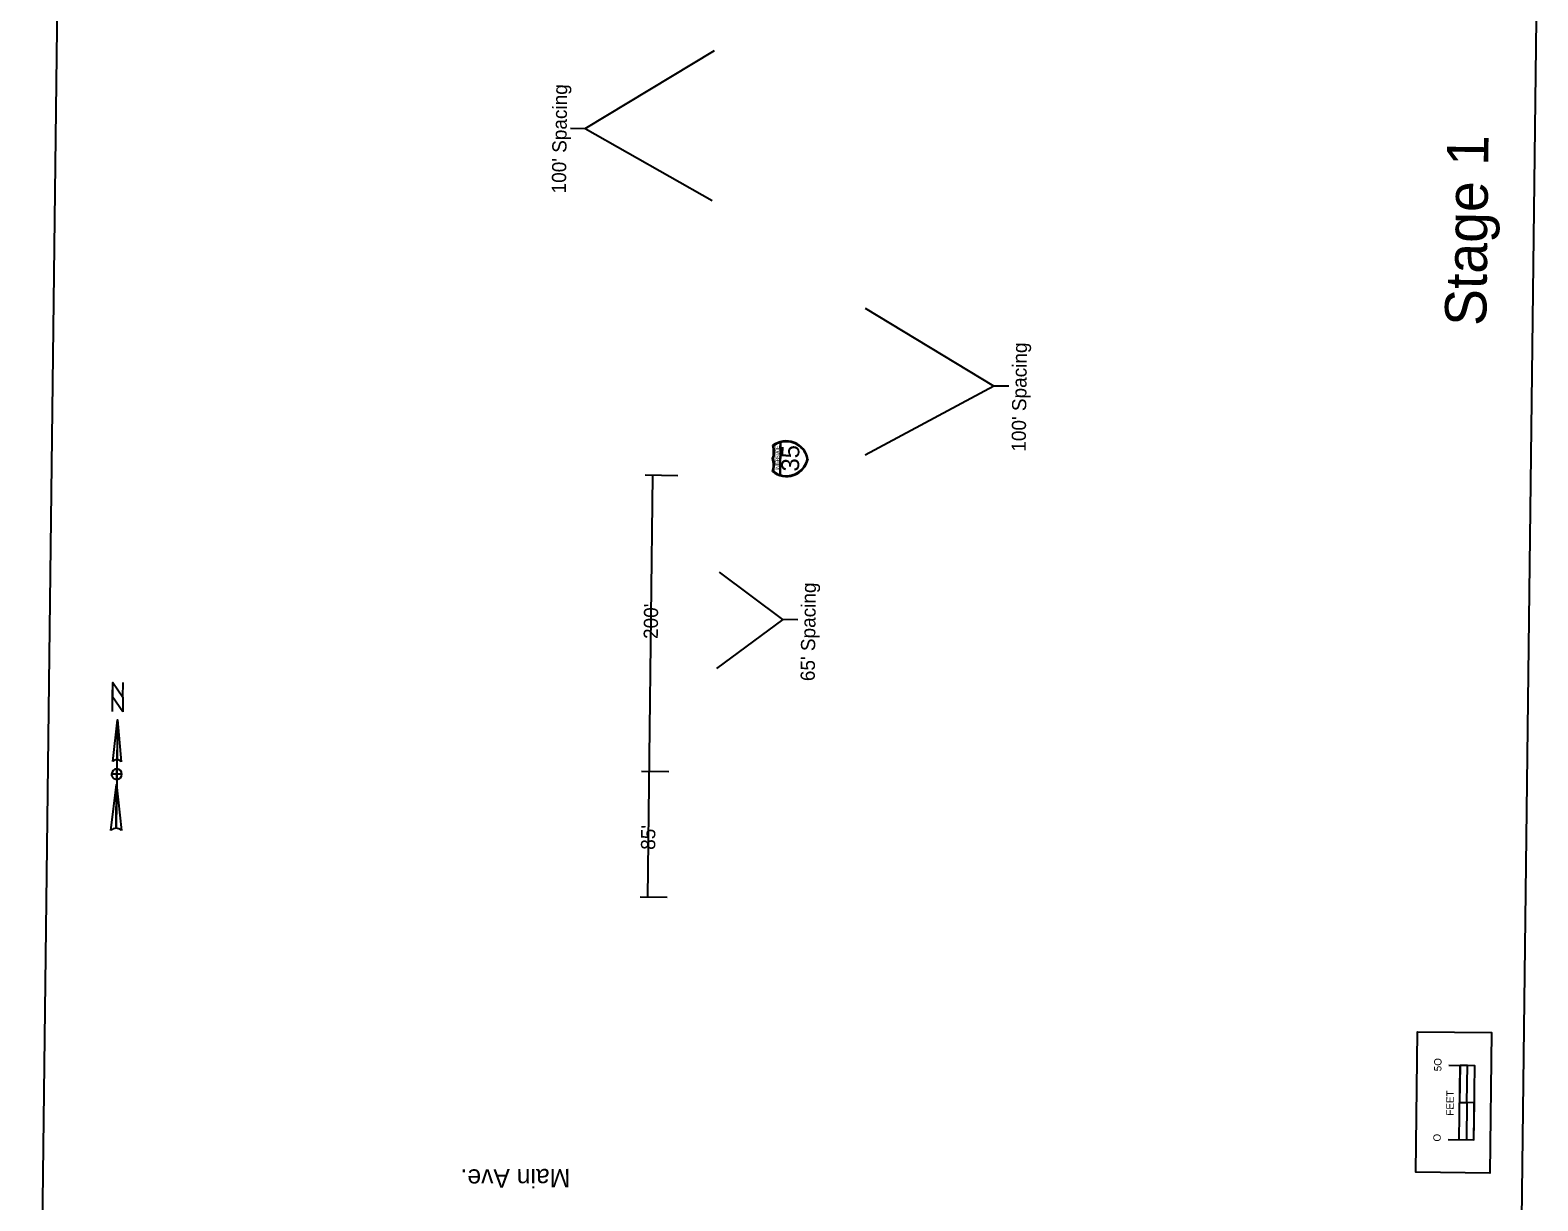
# Model space of a CAD drawing. Extents: x 4959127 to 4960275, y 3872379 to 3884458.
# Drawn here: x 4959182 to 4960201, y 3877574 to 3878365 of the extents above; entities that cross this region are included whole.
import ezdxf

# ---------------------------------------------------------------- set-up
doc = ezdxf.new("R2010")
doc.units = 0
for name, color, linetype in [('Cell', 7, 'Continuous'), ('dsnCellElements', 7, 'Continuous'), ('dsnCellsHighwaySymbols', 7, 'Continuous'), ('dsnCellsScaleBlock', 7, 'Continuous'), ('NamedBoundary', 7, 'Continuous'), ('SheetText', 7, 'Continuous'), ('Text', 7, 'Continuous')]:
    doc.layers.add(name, color=color, linetype=linetype)

msp = doc.modelspace()

# ---------------------------------------------------------------- linework, layer by layer
at = {"layer": 'Cell'}
for p, q in [((4959241.1, 3877898.6), (4959240.2, 3877825.4)), ((4959241.1, 3877898.6), (4959243.5, 3877870.4)), ((4959237.9, 3877870.5), (4959237.9, 3877870.5)), ((4959238, 3877870.7), (4959238.5, 3877871.3)), ((4959240.6, 3877858.5), (4959240.6, 3877858.5)), ((4959236.6, 3877824), (4959240.5, 3877855))]:
    msp.add_line(p, q, dxfattribs=at)
for points in [[(4959237.6, 3877904.3), (4959237.9, 3877924), (4959244.8, 3877914.1), (4959244.9, 3877923.9)], [(4959237.9, 3877870.5), (4959241.1, 3877898.6), (4959240.7, 3877871.9)], [(4959240.6, 3877858.5), (4959240.6, 3877862), (4959237.1, 3877862)], [(4959244.1, 3877862), (4959240.6, 3877862), (4959240.7, 3877865.5)], [(4959240.2, 3877825.4), (4959240.5, 3877855), (4959243.7, 3877823.9)]]:
    msp.add_lwpolyline(points, dxfattribs=at)
msp.add_lwpolyline([(4959244.7, 3877904.2), (4959237.7, 3877914.2), (4959237.9, 3877924), (4959244.8, 3877914.1)], close=True, dxfattribs=at)
for centre, radius, start, end in [((4959240.7, 3877868.3), 3.52, 89.3179, 142.4233), ((4959240.7, 3877868.3), 3.52, 36.1456, 89.3194), ((4959240.6, 3877862), 3.52, 89.2975, 179.2975), ((4959240.6, 3877862), 3.52, 179.2975, 269.2975), ((4959240.6, 3877862), 3.52, 269.2975, 359.2975), ((4959240.6, 3877862), 3.52, 359.2975, 89.2975), ((4959240.1, 3877820.3), 5.1, 89.2869, 132.9165), ((4959240.1, 3877820.3), 5.11, 45.6996, 89.2982)]:
    msp.add_arc(centre, radius, start, end, dxfattribs=at)
at = {"layer": 'dsnCellElements'}
msp.add_lwpolyline([(4960118.7, 3877592.9), (4960119.9, 3877687.9), (4960169.9, 3877687.3), (4960168.7, 3877592.3)], close=True, dxfattribs=at)
msp.add_lwpolyline([(4960118.7, 3877592.9), (4960119.9, 3877687.9), (4960169.9, 3877687.3), (4960168.7, 3877592.3)], close=True, dxfattribs=at)
at = {"layer": 'dsnCellsHighwaySymbols'}
for p, q in [((4959689, 3878086.1), (4959688.7, 3878064.4)), ((4959689.2, 3878064.2), (4959689.5, 3878086.2))]:
    msp.add_line(p, q, dxfattribs=at)
for centre, radius, start, end in [((4959669.6, 3878079.9), 15, 342.3065, 16.2887), ((4959693.1, 3878072.2), 15, 10.8347, 127.6287), ((4959669.6, 3878079.9), 15.5, 342.7231, 14.8585), ((4959693.1, 3878072.2), 14.5, 106.5608, 126.3017), ((4959693.2, 3878072.2), 14.5, 11.2271, 104.5442), ((4959669.5, 3878071.1), 15, 342.3065, 16.2887), ((4959693.2, 3878078.2), 15, 230.9665, 347.7605), ((4959669.5, 3878071), 15.5, 343.7366, 15.8721), ((4959693.2, 3878078.2), 14.5, 254.051, 347.368), ((4959693.2, 3878078.2), 14.5, 232.2935, 252.0342)]:
    msp.add_arc(centre, radius, start, end, dxfattribs=at)
at = {"layer": 'dsnCellsScaleBlock'}
msp.add_line((4960158.3, 3877639.9), (4960148.3, 3877640), dxfattribs=at)
msp.add_line((4960158.3, 3877639.9), (4960148.3, 3877640), dxfattribs=at)
for points in [[(4960168.7, 3877592.3), (4960118.7, 3877592.9), (4960119.9, 3877687.9), (4960169.9, 3877687.3)], [(4960153.2, 3877640), (4960153.6, 3877665), (4960148.6, 3877665), (4960148.3, 3877640)], [(4960158, 3877614.9), (4960158.3, 3877639.9), (4960153.2, 3877640), (4960152.9, 3877615)]]:
    msp.add_lwpolyline(points, close=True, dxfattribs=at)
for points in [[(4960140.5, 3877615.1), (4960158, 3877614.9), (4960158.6, 3877664.9), (4960141.1, 3877665.1)], [(4960148, 3877615), (4960148.6, 3877665)]]:
    msp.add_lwpolyline(points, dxfattribs=at)
at = {"layer": 'NamedBoundary'}
msp.add_lwpolyline([(4959182, 3876891.1), (4960182, 3876878.8), (4960201.2, 3878446.2), (4959201.3, 3878458.5)], close=True, dxfattribs=at)
at = {"layer": 'SheetText'}
for p, q in [((4959557.2, 3878298.5), (4959644.6, 3878351.1)), ((4959833.5, 3878124.3), (4959746.8, 3878176.7)), ((4959619.8, 3878063.7), (4959597.8, 3878064)), ((4959599.5, 3877778.7), (4959603, 3878063.9)), ((4959613.7, 3877863.5), (4959595.4, 3877863.7)), ((4959612.7, 3877778.5), (4959594.4, 3877778.8))]:
    msp.add_line(p, q, dxfattribs=at)
for points in [[(4959547.2, 3878298.6), (4959557.2, 3878298.5), (4959643, 3878249.8)], [(4959843.5, 3878124.2), (4959833.5, 3878124.3), (4959746.5, 3878077.7)], [(4959690.9, 3877966.6), (4959690.9, 3877966.6), (4959648, 3877998.5)], [(4959700.9, 3877966.4), (4959690.9, 3877966.6), (4959645.9, 3877933.5)]]:
    msp.add_lwpolyline(points, dxfattribs=at)

# ---------------------------------------------------------------- texts
at = {"layer": 'dsnCellsHighwaySymbols'}
for s, height, p in [('T', 2.5, (4959688.4, 3878080.1)), ('E', 2.5, (4959688.5, 3878081.8)), ('35', 12, (4959701.8, 3878066.5)), ('E', 2.5, (4959688.3, 3878071.8)), ('T', 2.5, (4959688.3, 3878070.1)), ('A', 2.5, (4959688.4, 3878078.4)), ('T', 2.5, (4959688.4, 3878077)), ('S', 2.5, (4959688.4, 3878075.2)), ('R', 2.5, (4959688.4, 3878073.4)), ('N', 2.5, (4959688.3, 3878068.3)), ('I', 2.5, (4959688.3, 3878067.4))]:
    msp.add_text(s, height=height, rotation=89.2975, dxfattribs=at).set_placement(p)
at = {"layer": 'dsnCellsScaleBlock'}
for s, p in [('5O', (4960136, 3877661.1)), ('FEET', (4960144.2, 3877631.1)), ('O', (4960135.5, 3877613.6))]:
    msp.add_text(s, height=5, rotation=89.2975, dxfattribs=at).set_placement(p)
at = {"layer": 'SheetText'}
for s, height, rotation, p in [("100' Spacing", 9.6, 89.2908, (4959544.2, 3878254.5)), ("100' Spacing", 9.6, 89.3042, (4959855, 3878079.9)), ("65' Spacing", 9.6, 89.3042, (4959712.4, 3877924.8)), ("200'", 9.6, 89.2975, (4959606.3, 3877953.3)), ("85'", 9.6, 89.2975, (4959604.5, 3877810.8)), ('Main Ave.', 12.48, 180.2975, (4959547.1, 3877595.2))]:
    msp.add_text(s, height=height, rotation=rotation, dxfattribs=at).set_placement(p)
at = {"layer": 'Text'}
msp.add_text('Stage 1', height=28, rotation=89.2975, dxfattribs=at).set_placement((4960166.3, 3878164.8))

doc.saveas('drawing.dxf')
